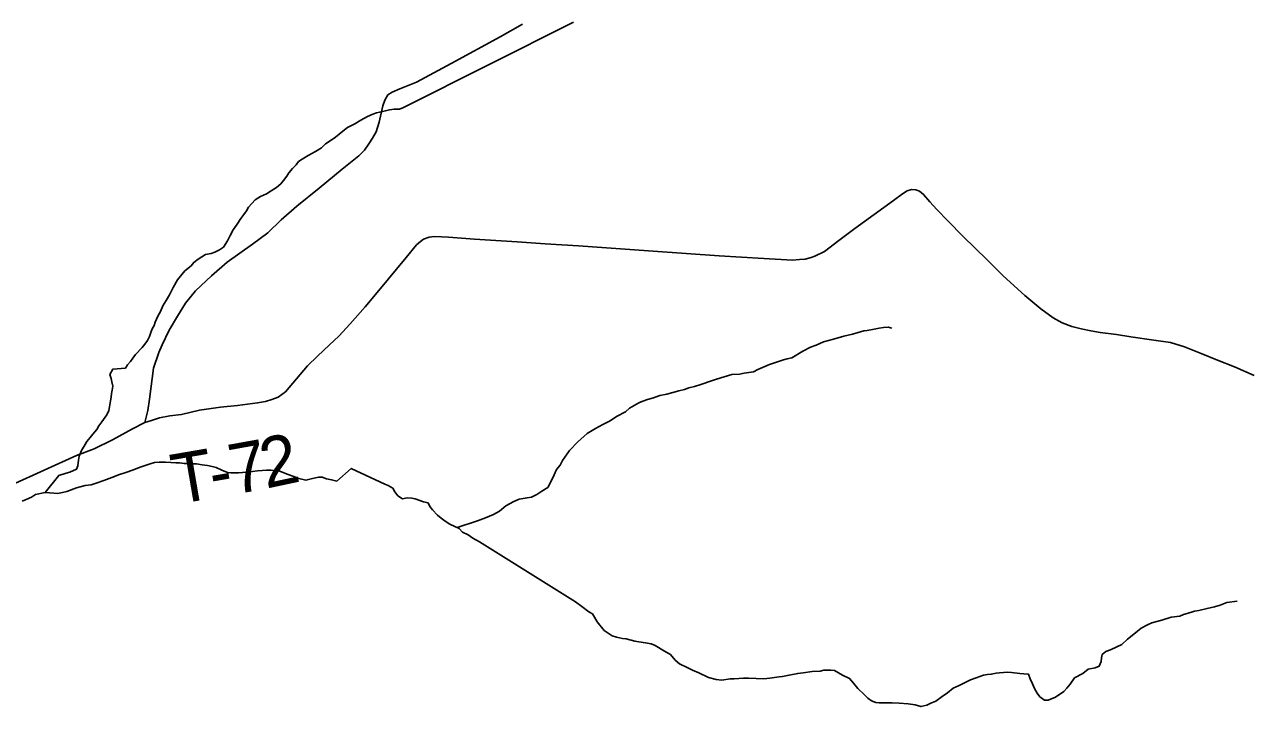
# Model space of a CAD drawing. Extents: x 0 to 34, y 0 to 22.
# Drawn here: x 24.872 to 26.261, y 18.187 to 18.961 of the extents above; entities that cross this region are included whole.
import ezdxf

# ---------------------------------------------------------------- set-up
doc = ezdxf.new("R2010")
doc.units = 0
for name, color, linetype in [('GM_X_Minor_River', 7, 'Continuous'), ('GM_X_Township_Road', 7, 'Continuous'), ('GM_X_Township_Road_Text', 7, 'Continuous')]:
    doc.layers.add(name, color=color, linetype=linetype)

msp = doc.modelspace()

# ---------------------------------------------------------------- linework, layer by layer
at = {"layer": 'GM_X_Minor_River'}
for points in [[(24.8957, 18.43), (24.9112, 18.449), (24.9195, 18.4516), (24.9237, 18.4528), (24.9316, 18.4562), (24.9331, 18.46), (24.9335, 18.4665), (24.9346, 18.471), (24.9376, 18.4782), (24.9403, 18.4824), (24.9433, 18.4877), (24.9471, 18.4923), (24.9501, 18.4961), (24.9546, 18.5014), (24.9569, 18.5056), (24.9603, 18.5101), (24.9659, 18.5181), (24.9682, 18.5227), (24.9689, 18.5272), (24.9701, 18.5337), (24.9708, 18.5379), (24.9712, 18.542), (24.9719, 18.5458), (24.9727, 18.5504), (24.9715, 18.5553), (24.9707, 18.5591), (24.9692, 18.5637), (24.9726, 18.5697), (24.987, 18.5709), (24.9893, 18.5747), (24.9927, 18.5785), (24.9953, 18.5823), (24.9983, 18.5865), (25.0062, 18.5945), (25.0089, 18.5983), (25.0119, 18.6024), (25.0145, 18.607), (25.0157, 18.6115), (25.0172, 18.6157), (25.0198, 18.6195), (25.0209, 18.6233), (25.024, 18.6298), (25.027, 18.6351), (25.0296, 18.6415), (25.0334, 18.6476), (25.0371, 18.6541), (25.0413, 18.6624), (25.0462, 18.6712), (25.0511, 18.6773), (25.0545, 18.6814), (25.0617, 18.6871), (25.0647, 18.6909), (25.0696, 18.6947), (25.0779, 18.7001), (25.0844, 18.7012), (25.0885, 18.7027), (25.0938, 18.7054), (25.0984, 18.7081), (25.1029, 18.7153), (25.1059, 18.7214), (25.1093, 18.7278), (25.1138, 18.7343), (25.118, 18.7407), (25.1214, 18.7453), (25.1244, 18.7495), (25.1267, 18.7537), (25.1342, 18.762), (25.1406, 18.7658), (25.1471, 18.7689), (25.1527, 18.7723), (25.1588, 18.7761), (25.1637, 18.7803), (25.1667, 18.7841), (25.1705, 18.7887), (25.1728, 18.7925), (25.1769, 18.7974), (25.1811, 18.8016), (25.1837, 18.8054), (25.1879, 18.808), (25.1947, 18.8122), (25.203, 18.8168), (25.2098, 18.821), (25.2143, 18.8255), (25.2208, 18.8297), (25.2257, 18.8331), (25.2321, 18.8385), (25.2393, 18.8442), (25.2476, 18.8484), (25.2544, 18.8526), (25.262, 18.8567), (25.2681, 18.8594), (25.2722, 18.8609), (25.2824, 18.8632), (25.287, 18.864), (25.2923, 18.8648), (25.2984, 18.8648), (25.3029, 18.8667), (25.4959, 18.9638)], [(25.3637, 18.3901), (25.3869, 18.3976), (25.396, 18.401), (25.4051, 18.4048), (25.4119, 18.4086), (25.4191, 18.4147), (25.4281, 18.4197), (25.4342, 18.4223), (25.4433, 18.4239), (25.4482, 18.4246), (25.4543, 18.4277), (25.4599, 18.4315), (25.4667, 18.4353), (25.4713, 18.444), (25.4739, 18.4497), (25.4769, 18.4558), (25.4807, 18.4607), (25.4837, 18.4661), (25.4916, 18.4775), (25.5011, 18.4873), (25.5117, 18.4968), (25.5211, 18.5026), (25.5294, 18.5071), (25.5378, 18.5113), (25.5449, 18.5159), (25.5552, 18.5212), (25.5597, 18.5254), (25.5703, 18.5315), (25.5748, 18.5334), (25.5801, 18.5353), (25.5869, 18.5372), (25.5941, 18.5399), (25.6021, 18.5414), (25.6157, 18.5452), (25.6222, 18.5468), (25.6271, 18.5487), (25.6335, 18.5502), (25.6407, 18.5525), (25.6528, 18.5567), (25.6585, 18.5586), (25.6759, 18.5636), (25.6846, 18.5643), (25.6899, 18.5651), (25.7005, 18.5667), (25.7055, 18.5693), (25.7187, 18.575), (25.7346, 18.5804), (25.7388, 18.5815), (25.7441, 18.5827), (25.7565, 18.5903), (25.7652, 18.5949), (25.7717, 18.5971), (25.78, 18.601), (25.7914, 18.604), (25.8031, 18.6071), (25.8129, 18.6094), (25.8258, 18.6132), (25.8296, 18.6136), (25.8357, 18.6147), (25.8432, 18.6163), (25.8482, 18.617), (25.8535, 18.6174), (25.8576, 18.6163)], [(24.8696, 18.42), (24.8741, 18.4219), (24.8802, 18.4246), (24.8847, 18.4277), (24.8957, 18.43), (24.9056, 18.4292), (24.9097, 18.4288), (24.9154, 18.43), (24.9203, 18.4311), (24.9313, 18.435), (24.9412, 18.4376), (24.948, 18.4384), (24.9537, 18.4403), (24.9624, 18.4434), (24.9714, 18.4468), (24.9802, 18.4502), (24.9862, 18.4521), (24.9961, 18.4556), (25.0006, 18.4575), (25.0059, 18.4594), (25.015, 18.4624), (25.0199, 18.464), (25.0252, 18.4644), (25.0324, 18.4644), (25.0385, 18.464), (25.0442, 18.4636), (25.0483, 18.4633), (25.0536, 18.4629), (25.0582, 18.4629), (25.062, 18.4625), (25.0676, 18.4622), (25.0741, 18.4614), (25.0802, 18.4603), (25.0855, 18.4592), (25.09, 18.458), (25.0965, 18.455), (25.1029, 18.4524), (25.1067, 18.452), (25.1154, 18.452), (25.1245, 18.4528), (25.1313, 18.4536), (25.137, 18.4543), (25.1423, 18.4547), (25.1472, 18.4551), (25.1522, 18.4551), (25.1582, 18.4544), (25.1624, 18.454), (25.167, 18.4521), (25.1719, 18.4502), (25.1772, 18.4484), (25.184, 18.4457), (25.192, 18.4438), (25.1981, 18.4454), (25.2064, 18.4473), (25.2106, 18.4473), (25.2155, 18.4454), (25.2212, 18.4443), (25.2272, 18.4428), (25.2435, 18.4572), (25.2818, 18.4391)], [(25.2818, 18.4391), (25.2856, 18.4376), (25.2909, 18.4346), (25.2932, 18.4304), (25.2963, 18.4262), (25.3019, 18.4228), (25.3069, 18.4236), (25.3122, 18.4232), (25.316, 18.4225), (25.3258, 18.4191), (25.3308, 18.4179), (25.333, 18.4138), (25.3357, 18.41), (25.3414, 18.4039), (25.3456, 18.4005), (25.3501, 18.3971), (25.3555, 18.3937), (25.3612, 18.3914), (25.3661, 18.3888), (25.3699, 18.3846), (25.3763, 18.3816), (25.3817, 18.3778), (25.3892, 18.374), (25.4982, 18.3056), (25.5054, 18.3003), (25.5134, 18.2942), (25.5176, 18.292), (25.5199, 18.2882), (25.5229, 18.2829), (25.5309, 18.273), (25.54, 18.267), (25.5449, 18.2655), (25.5518, 18.264), (25.5559, 18.2636), (25.5658, 18.261), (25.5703, 18.2602), (25.5779, 18.2591), (25.5844, 18.258), (25.5889, 18.2561), (25.5995, 18.2496), (25.6064, 18.2459), (25.6117, 18.2394), (25.6166, 18.2353), (25.6261, 18.2307), (25.6314, 18.2281), (25.6386, 18.2251), (25.6493, 18.2198), (25.658, 18.2175), (25.6644, 18.2168), (25.6739, 18.2183), (25.6784, 18.2183), (25.6891, 18.2191), (25.6947, 18.2191), (25.7122, 18.2184), (25.719, 18.2192), (25.7296, 18.2207), (25.7334, 18.2211), (25.741, 18.2226), (25.7508, 18.2245), (25.7569, 18.2253), (25.7671, 18.2268), (25.7762, 18.2272), (25.7804, 18.228), (25.7883, 18.228), (25.7925, 18.2277), (25.8016, 18.2224), (25.8096, 18.2186), (25.8141, 18.2133), (25.8191, 18.2072), (25.8263, 18.2004), (25.8305, 18.1962), (25.8346, 18.1932), (25.8396, 18.1913), (25.8434, 18.191), (25.8532, 18.191), (25.8581, 18.191), (25.8661, 18.1906), (25.8763, 18.1899), (25.8843, 18.1888), (25.8907, 18.1869), (25.8976, 18.1884), (25.9021, 18.1907), (25.9078, 18.193), (25.915, 18.1983), (25.921, 18.2025), (25.9274, 18.2078), (25.9342, 18.2109), (25.9471, 18.2173), (25.9535, 18.2196), (25.9619, 18.2223), (25.9664, 18.2231), (25.9706, 18.2235), (25.9763, 18.2246), (25.9801, 18.225), (25.9891, 18.2258), (25.9937, 18.2254), (26.0032, 18.2243), (26.0077, 18.2239), (26.013, 18.2235), (26.0149, 18.2182), (26.0176, 18.2126)], [(26.0176, 18.2126), (26.0199, 18.2072), (26.0226, 18.2019), (26.026, 18.1978), (26.0313, 18.194), (26.0351, 18.194), (26.0438, 18.1974), (26.0529, 18.2039), (26.0566, 18.2077), (26.0604, 18.2123), (26.0653, 18.2195), (26.0748, 18.2244), (26.0808, 18.2294), (26.0888, 18.2309), (26.0933, 18.2328), (26.0956, 18.2381), (26.096, 18.2423), (26.0967, 18.2461), (26.1009, 18.2495), (26.1062, 18.2514), (26.1134, 18.2545), (26.119, 18.2572), (26.1255, 18.2632), (26.1326, 18.2689), (26.1409, 18.2758), (26.1481, 18.2796), (26.1531, 18.2819), (26.1572, 18.283), (26.1644, 18.2849), (26.175, 18.2884), (26.1849, 18.2895), (26.189, 18.2914), (26.1932, 18.2926), (26.2015, 18.2953), (26.2064, 18.296), (26.2159, 18.2983), (26.2242, 18.3002), (26.2307, 18.3021), (26.2382, 18.3048), (26.25, 18.3064)]]:
    msp.add_lwpolyline(points, dxfattribs=at)
at = {"layer": 'GM_X_Township_Road'}
for points in [[(24.8579, 18.4385), (24.9316, 18.4717), (24.9515, 18.4793), (24.9724, 18.4896), (24.9951, 18.502), (25.0091, 18.5093), (25.0123, 18.5229), (25.0144, 18.5356), (25.019, 18.5709), (25.0248, 18.5888), (25.0287, 18.5976), (25.0368, 18.614), (25.0462, 18.6299), (25.0552, 18.6446), (25.0667, 18.6587), (25.0847, 18.6758), (25.1025, 18.6914), (25.1313, 18.7117), (25.1486, 18.7246), (25.164, 18.7394), (25.1816, 18.7548), (25.2071, 18.7751), (25.2332, 18.7968), (25.2521, 18.8118), (25.2586, 18.8182), (25.2636, 18.8254), (25.2676, 18.8319), (25.2717, 18.8392), (25.2752, 18.8503), (25.2793, 18.8685), (25.2816, 18.8752), (25.2851, 18.881), (25.2899, 18.8842), (25.2987, 18.8881), (25.3176, 18.8955), (25.357, 18.9167), (25.4128, 18.9471), (25.4382, 18.9614)], [(25.0091, 18.5093), (25.0167, 18.5116), (25.0256, 18.5146), (25.0374, 18.5168), (25.0508, 18.5185), (25.0713, 18.5233), (25.095, 18.5266), (25.1144, 18.5286), (25.1372, 18.5314), (25.1462, 18.5331), (25.1533, 18.5355), (25.1605, 18.5381), (25.1688, 18.544), (25.194, 18.5734), (25.2051, 18.5845), (25.219, 18.5973), (25.2295, 18.6071), (25.2425, 18.6212), (25.2593, 18.6406), (25.2747, 18.6589), (25.3058, 18.6967), (25.3178, 18.7109), (25.3221, 18.7148), (25.3258, 18.7174), (25.3319, 18.7196), (25.3382, 18.7202), (25.3539, 18.7198), (25.3837, 18.7174), (25.432, 18.7143), (25.4637, 18.7119), (25.5018, 18.7098), (25.5867, 18.7037), (25.6617, 18.6984), (25.7122, 18.6954), (25.745, 18.6937), (25.7526, 18.6941), (25.7592, 18.6948), (25.7659, 18.6965), (25.7703, 18.698), (25.7811, 18.7035), (25.7974, 18.7159), (25.8157, 18.7296), (25.8594, 18.7613), (25.8697, 18.7687), (25.8751, 18.7722), (25.8801, 18.7737), (25.8849, 18.7735), (25.8892, 18.7718), (25.8938, 18.7681), (25.9008, 18.7598), (25.9088, 18.7509), (25.9212, 18.7383), (25.9386, 18.7202), (25.966, 18.6939), (25.9843, 18.6756), (26.0087, 18.6536), (26.0269, 18.6384), (26.0411, 18.6282), (26.0513, 18.6223), (26.062, 18.6184), (26.0726, 18.6156), (26.0837, 18.6134), (26.0944, 18.6114), (26.1129, 18.609), (26.1292, 18.6064), (26.1555, 18.6027), (26.1744, 18.5999), (26.1901, 18.5953), (26.209, 18.5877), (26.2277, 18.5799), (26.2471, 18.5723), (26.2695, 18.5625)]]:
    msp.add_lwpolyline(points, dxfattribs=at)

# ---------------------------------------------------------------- texts
at = {"layer": 'GM_X_Township_Road_Text'}
for s, rotation, p in [('2', 11.9914, (25.1465, 18.434)), ('T', 9.7498, (25.0448, 18.4162)), ('7', 10.1721, (25.1101, 18.4274)), ('-', 9.8229, (25.0867, 18.4234))]:
    msp.add_text(s, height=0.0568, rotation=rotation, dxfattribs=at).set_placement(p)

doc.saveas('drawing.dxf')
